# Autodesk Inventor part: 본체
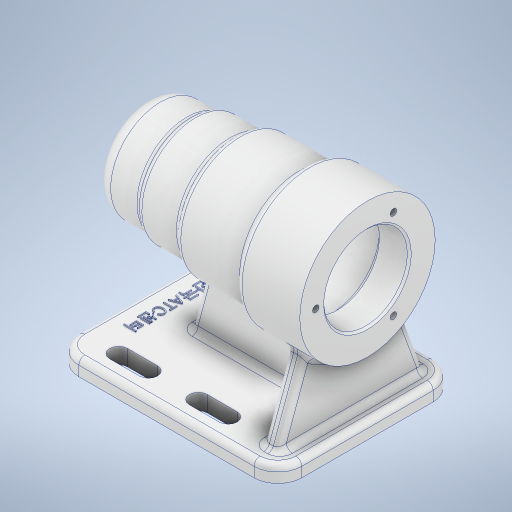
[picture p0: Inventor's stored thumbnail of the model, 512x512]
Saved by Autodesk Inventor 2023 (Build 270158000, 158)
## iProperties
Created: 2022-07
Part Number: 본체
Material: 알루미늄 6061
Document SubType Name: Modeling
Designer: owner
Density: 2.7 g/cm^3
Appearance: 알루미늄 - 평지
Mass: 693.204 g
Surface Area: 699.307 cm^2
Volume: 256.742 cm^3
Author: owner
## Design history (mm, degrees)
sketch "스케치1"
  geometry: L1 (0, 0)-(112, 0); L2 (0, 0)-(0, 25); L3 (0, 25)-(24, 25); L4 (24, 25)-(24, 27); L5 (24, 27)-(46, 27); L6 (46, 27)-(46, 30); L7 (46, 30)-(80, 30); L8 (80, 30)-(80, 34); L9 (80, 34)-(112, 34); L10 (112, 34)-(112, 21); L11 (112, 21)-(97, 21); L12 (97, 21)-(97, 21); L13 (94, 24)-(46, 24); L14 (43, 21)-(43, 21); L15 (43, 21)-(31.3, 21); L16 (31, 20.7)-(31, 17.5); L17 (31, 17.5)-(13.3, 17.5); L18 (13, 17.2)-(13, 16); L19 (13, 16)-(9.3, 16); L20 (9, 15.7)-(9, 10.5); L21 (9, 10.5)-(9, 10.5); L22 (6, 7.5)-(6, 0); A1 r 3 centre (9, 7.5) between (9, 10.5) and (6, 7.5); A2 r 0.3 centre (9.3, 15.7) between (9.3, 16) and (9, 15.7); A3 r 0.3 centre (13.3, 17.2) between (13.3, 17.5) and (13, 17.2); A4 r 0.3 centre (31.3, 20.7) between (31.3, 21) and (31, 20.7); A5 r 3 centre (46, 21) between (46, 24) and (43, 21); A6 r 3 centre (94, 21) between (97, 21) and (94, 24); 9 further points
  constraints: 44 end point, 19 perpendicular, 14 point on line, 12 point on circle, 12 tangent, 6 centre point, 2 equal radius, 1 horizontal, 1 parallel, 1 vertical
  dimensions: "d0" = 112 distance of L1.start L1.end; "d1" = 42 diameter of L11 L1; "d2" = 48 diameter of L13 L1; "d3" = 68 diameter of L9 L1; "d4" = 42 diameter of L15 L1; "d5" = 35 diameter of L17 L1; "d6" = 32 diameter of L19 L1; "d7" = 21 diameter of L21 L1; "d8" = 50 diameter of L3 L1; "d9" = 54 diameter of L5 L1; "d10" = 60 diameter of L7 L1; "d11" = 24 distance of L2.end L3.end; "d12" = 46 distance between parallel lines of L2 L6; "d13" = 80 distance between parallel lines of L2 L8; "d14" = 15 distance of L10.end L11.end; "d15" = 54 distance of point (97, 24) point (43, 24); "d16" = 12 distance of L14.end point (31, 21); "d17" = 18 distance of L16.end point (13, 17.5); "d18" = 3 distance of L20.end point (6, 10.5); "d19" = 4 distance of L18.end point (9, 16); "d20" = 3 radius of A1; "d21" = 0.3 radius of A2; "d86" = 0.3 radius of A4; "d87" = 3 radius of A5
revolve "회전1" sketch "스케치1" stored, may be unused: angle "d22" = 90 deg
fillet "모깎기1" dims "d23" = 8
node "작업 평면1"
sketch "스케치2"
  geometry: L1 (0, -45)-(-112, -45); L2 (-112, -45)-(-112, 45); L3 (-112, 45)-(0, 45); L4 (0, 45)-(0, -45); L5 (0, 17)-(0, -17) reference; L6 (-112, 34)-(-112, -34) reference; 2 further points
  constraints: 8 end point, 2 parallel, 1 horizontal, 1 midpoint, 1 perpendicular
  dimensions: "d25" = 0 distance between parallel lines of L4 L5; "d26" = 0 distance between parallel lines of L6 L2; "d27" = 90 distance of L3.end L1.start; "d28" = 45 distance from line of point (0, 0) L1
extrude "돌출1" join sketch "스케치2" distance "d29" = 8; taper "d30" = 0 deg
fillet "모깎기2" dims "d31" = 12
fillet "모깎기3" dims "d32" = 3
sketch "스케치3"
  geometry: L1 (20, 33)-(35, 33); L2 (20, 28.5)-(35, 28.5); L3 (35, 37.5)-(20, 37.5); L4 (20, -33)-(35, -33); L5 (20, -37.5)-(35, -37.5); L6 (35, -28.5)-(20, -28.5); L7 (60, -33)-(75, -33); L8 (60, -37.5)-(75, -37.5); L9 (75, -28.5)-(60, -28.5); L10 (60, 33)-(75, 33); L11 (60, 28.5)-(75, 28.5); L12 (75, 37.5)-(60, 37.5); L13 (112, -33)-(112, 33) reference; L14 (0, 33)-(0, -33) reference; A1 r 4.5 centre (20, 33) between (20, 37.5) and (20, 28.5); A2 r 4.5 centre (35, 33) between (35, 28.5) and (35, 37.5); A3 r 4.5 centre (20, -33) between (20, -28.5) and (20, -37.5); A4 r 4.5 centre (35, -33) between (35, -37.5) and (35, -28.5); A5 r 4.5 centre (60, -33) between (60, -28.5) and (60, -37.5); A6 r 4.5 centre (75, -33) between (75, -37.5) and (75, -28.5); A7 r 4.5 centre (60, 33) between (60, 37.5) and (60, 28.5); A8 r 4.5 centre (75, 33) between (75, 28.5) and (75, 37.5); 5 further points
  constraints: 32 end point, 16 point on circle, 16 tangent, 8 centre point, 5 parallel, 4 midpoint, 4 point on line, 1 horizontal
  dimensions: "d33" = 9 diameter of A2; "d34" = 9 diameter of A4; "d35" = 9 diameter of A6; "d36" = 9 diameter of A8; "d39" = 33 distance from line of point (0, 0) L1; "d40" = 33 distance from line of L4 point (0, 0); "d41" = 15 distance of L4.start L4.end; "d42" = 15 distance of L7.start L7.end; "d43" = 25 distance of L7.start L4.end; "d44" = 15 distance of L1.start L1.end; "d45" = 15 distance of L10.start L10.end; "d46" = 25 distance of L10.start L1.end; "d100" = 20 distance from line of L14 L1.start; "d101" = 20 distance from line of L14 L4.start
extrude "돌출2" cut sketch "스케치3" stored distance "d47" = 8; taper "d48" = 0 deg
sketch "스케치4"
  geometry: L1 (27, 4)-(104, 4); L2 (104, 4)-(104, -4); L3 (104, -4)-(27, -4); L4 (27, -4)-(27, 4); L5 (112, -33)-(112, 33) reference; 1 further point
  constraints: 8 end point, 2 parallel, 1 horizontal, 1 perpendicular
  dimensions: "d49" = 8 distance between parallel lines of L5 L2; "d50" = 8 distance between parallel lines of L3 L1; "d51" = 4 distance from line of point (0, 0) L3; "d52" = 77 distance of L1.start L1.end
extrude "돌출3" join sketch "스케치4" stored distance "d53" = 10; taper "d54" = 0 deg
feature "면 기울기1" dims angle "d55" = 15 deg
sketch "스케치5"
  geometry: L1 (96, 37)-(104, 37); L2 (104, 37)-(104, -37); L3 (104, -37)-(96, -37); L4 (96, -37)-(96, 37); L5 (112, -33)-(112, 33) reference; L6 (100, 45)-(12, 45) reference; L7 (12, -45)-(100, -45) reference; 3 further points
  constraints: 8 end point, 2 midpoint, 2 parallel, 1 horizontal, 1 perpendicular
  dimensions: "d56" = 8 distance of L1.start L1.end; "d57" = 8 distance between parallel lines of L5 L2; "d91" = 8 distance from line of L6 point (100, 37); "d92" = 8 distance from line of L7 point (100, -37)
fillet "모깎기4" dims "d64" = 3
fillet "모깎기7" dims "d67" = 3
sketch "스케치6"
  geometry: 2 further points
  constraints: 1 other
  dimensions: "d68" = 0 vertical distance of point (0, 0) point (12, 0); "d69" = 12 distance of point (0, 0) point (12, 0)
feature "엠보싱1" sketch "스케치6" dims "d0" = 112, "d1" = 42, "d2" = 48, "d3" = 68, "d4" = 42, "d5" = 35, "d6" = 32, "d7" = 21, "d8" = 50, "d9" = 54, "d10" = 60, "d11" = 24, "d12" = 46, "d13" = 80, "d14" = 15, "d15" = 54, "d16" = 12, "d17" = 18, "d18" = 3, "d19" = 4, "d20" = 3, "d21" = 0.3, "d70" = 0.5, "d71" = 0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
sketch "스케치7"
  geometry: C1 r 10.5 at (0, 0) reference; C2 r 26 at (0, 0); 5 further points
  constraints: 1 centre point, 1 coincident, 1 horizontal alignment, 5 other
  dimensions: "d73" = 0 vertical distance of point (0, 0) point (-26, 0); "d76" = 360 deg dimension on point (0, 0) point (-26, 0) (derived); "d78" = 52 diameter of C2
hole "구멍1" sketch "스케치7" at (-26, 0), (13, -22.517), (13, 22.517) diameter "d79" = 3.242; stored, may be unused: countersink angle "d83" = 90 deg, drill point angle "d85" = 118 deg; dims "d80" = 8, "d81" = 4, "d82" = 2, "d84" = 11
chamfer "모따기1" distance "d88" = 1; stored, may be unused: second distance "d89" = 2, angle "d90" = 45 deg
extrude "돌출5" join sketch "스케치5" distance "d93" = 38; taper "d94" = 0 deg
feature "면 기울기4" dims angle "d95" = 20 deg
feature "면 기울기5" dims angle "d96" = 20 deg
fillet "모깎기8" dims "d97" = 3
fillet "모깎기9" dims "d98" = 3
fillet "모깎기10" dims "d99" = 3
node "솔리드1"
feature "A9D066F2-1C7D-4E18-AEED-F7BC21143FA4" dims "d79" = 3.242, "d80" = 8, "d81" = 4, "d82" = 2, "d83" = 90 deg, "d84" = 11, "d85" = 118 deg
